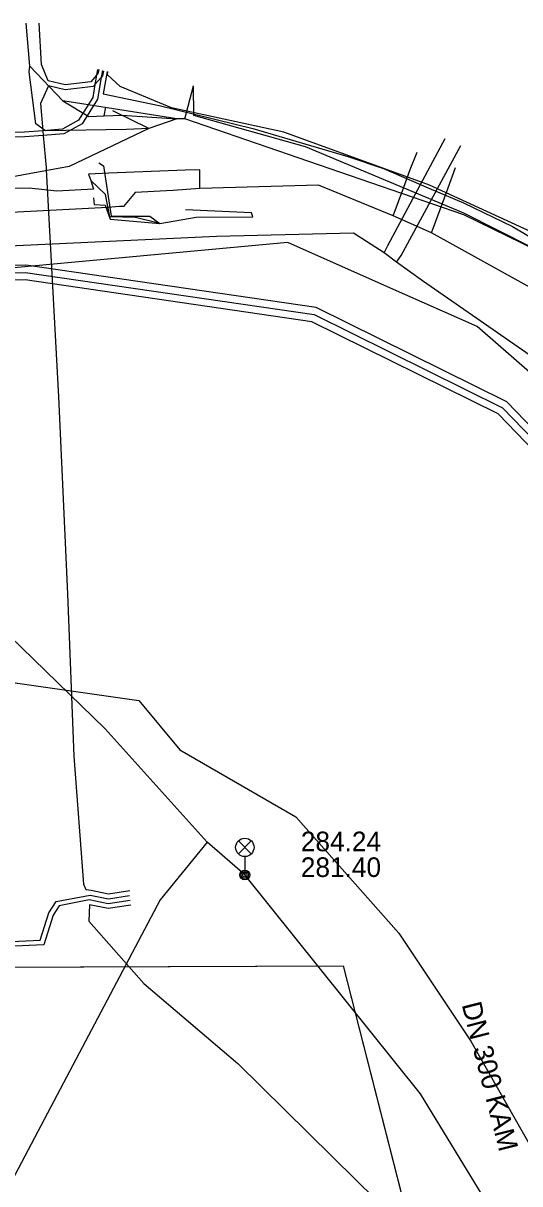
# Model space of a CAD drawing. Extents: x -599854 to -599675, y -1160809 to -1160543.
# Drawn here: x -599765.66 to -599745.4, y -1160591.29 to -1160543.95 of the extents above; entities that cross this region are included whole.
import ezdxf

# ---------------------------------------------------------------- set-up
doc = ezdxf.new("R2010")
doc.units = 0
for name, color, linetype in [('BKOM-ODVODNENI_trasa sítě', 7, 'Continuous'), ('BVK-VODOVOD_trasa sítě', 7, 'Continuous'), ('BVK-VODOVOD_trasa zrušené sítě', 7, 'Continuous'), ('CETIN_kabel podzemní', 7, 'Continuous'), ('CETIN_kabel podzemní neprovozovaný', 7, 'Continuous'), ('DESTOVA-NEPROVOZOVANA_popisy', 7, 'Continuous'), ('DESTOVA_trasa neprovozované sítě', 7, 'Continuous'), ('DPMB_kabel', 7, 'Continuous'), ('DPMB_kyneta', 7, 'Continuous'), ('DSP-JEDNOTNA-BVK_trasa sítě', 7, 'Continuous'), ('EON-NN_kabel', 7, 'Continuous'), ('EON-NN_kabel zrušené sítě', 7, 'Continuous'), ('INNOGY-KABELY_uzemnění', 7, 'Continuous'), ('INNOGY-NTL_trasa sítě', 7, 'Continuous'), ('INNOGY-STL_trasa sítě', 7, 'Continuous'), ('TSB_kabel VO', 7, 'Continuous'), ('TSB_lampy VO', 7, 'Continuous')]:
    doc.layers.add(name, color=color, linetype=linetype)

msp = doc.modelspace()

# ---------------------------------------------------------------- linework, layer by layer
at = {"layer": 'BKOM-ODVODNENI_trasa sítě'}
for points in [[(-599792.21, -1160582.54), (-599790.8, -1160582.535), (-599775.06, -1160582.479), (-599766.92, -1160582.451), (-599752.61, -1160582.4)], [(-599752.61, -1160582.4), (-599748.203, -1160599.656), (-599748.115, -1160600), (-599747.14, -1160603.82)]]:
    msp.add_lwpolyline(points, dxfattribs=at)
at = {"layer": 'BVK-VODOVOD_trasa sítě'}
for points in [[(-599750.93, -1160553.31), (-599750.79, -1160553.02), (-599748.448, -1160548.656)], [(-599750.43, -1160553.69), (-599750.24, -1160553.43), (-599747.809, -1160548.936)], [(-599719.633, -1160602.967), (-599720.5, -1160603.21), (-599721.46, -1160603.05), (-599723.09, -1160601.91), (-599724.27, -1160595.77), (-599725.34, -1160590.19), (-599725.75, -1160588.02), (-599726.33, -1160585.11), (-599727.19, -1160580.77), (-599730.66, -1160575.71), (-599731.23, -1160574.92), (-599731.73, -1160574.22), (-599732.69, -1160572.85), (-599736.99, -1160566.71), (-599739.23, -1160561.6), (-599744.81, -1160557.63), (-599749.37, -1160554.46), (-599750.43, -1160553.69), (-599750.93, -1160553.31), (-599752.19, -1160552.51), (-599757.77, -1160552.65), (-599772.65, -1160553.34)]]:
    msp.add_lwpolyline(points, dxfattribs=at)
at = {"layer": 'BVK-VODOVOD_trasa zrušené sítě'}
msp.add_lwpolyline([(-599723.312, -1160596.189), (-599723.552, -1160595.075), (-599725.385, -1160585.124), (-599727.088, -1160577.648), (-599730.061, -1160573.561), (-599730.185, -1160573.396), (-599730.663, -1160572.731), (-599734.747, -1160567.144), (-599747.147, -1160556.314), (-599750.794, -1160554.698), (-599754.863, -1160552.892), (-599773.118, -1160554.584), (-599787.156, -1160555.886), (-599789.075, -1160557.142), (-599798.149, -1160563.04), (-599806.144, -1160568.237), (-599808.168, -1160571.846), (-599815.66, -1160586.425), (-599816.228, -1160587.481)], dxfattribs=at)
at = {"layer": 'CETIN_kabel podzemní'}
for points in [[(-599765.39, -1160545.7), (-599765.5368, -1160543.9495)], [(-599760.54, -1160548.25), (-599761.45, -1160548.29), (-599764.75, -1160548.34), (-599765.14, -1160548.05), (-599765.42, -1160545.93), (-599765.39, -1160545.7)], [(-599764.05, -1160547.12), (-599765.39, -1160545.7)], [(-599759.07, -1160547.85), (-599758.71, -1160546.51)], [(-599764.05, -1160547.12), (-599762.984, -1160547.756)], [(-599759.39, -1160547.85), (-599764.05, -1160547.12)], [(-599762.353, -1160547.732), (-599762.287, -1160547.377)], [(-599760.54, -1160548.25), (-599762.01, -1160547.53)], [(-599760.54, -1160548.25), (-599763.79, -1160549.79), (-599775.39, -1160551.91), (-599776.73, -1160551.13), (-599777.24, -1160548.01), (-599779.6, -1160547.75), (-599787.47, -1160549.87), (-599795.94, -1160553.78), (-599800.44, -1160556.65), (-599809.68, -1160565.19), (-599817.48, -1160577.77), (-599818.39, -1160579.19)], [(-599762.984, -1160547.756), (-599762.353, -1160547.732)], [(-599762.353, -1160547.732), (-599761.618, -1160547.704)], [(-599761.618, -1160547.704), (-599759.39, -1160547.85)], [(-599759.39, -1160547.85), (-599760.54, -1160548.25)], [(-599759.07, -1160547.85), (-599759.39, -1160547.85)], [(-599743.51, -1160553.8), (-599747.69, -1160551.77), (-599759.07, -1160547.85)], [(-599814.4, -1160581.07), (-599811.3, -1160581.33), (-599803.39, -1160585.07), (-599799.44, -1160586.24), (-599796.45, -1160587.12), (-599794.41, -1160586.52), (-599780.55, -1160576.54), (-599778.97, -1160574.64), (-599776.87, -1160571.64), (-599775.34, -1160571.18), (-599766.27, -1160570.81), (-599760.94, -1160571.57), (-599759.27, -1160573.58), (-599754.54, -1160576.32), (-599750.34, -1160581.07), (-599747.4, -1160585.47), (-599742.37, -1160594.32)]]:
    msp.add_lwpolyline(points, dxfattribs=at)
at = {"layer": 'CETIN_kabel podzemní neprovozovaný'}
for points in [[(-599754.14, -1160548.99), (-599758.7, -1160547.71), (-599758.71, -1160546.51)], [(-599720.38, -1160590.29), (-599722.4, -1160580.45), (-599729.47, -1160568.06), (-599734.57, -1160560.31), (-599743.51, -1160553.8), (-599747.69, -1160551.7), (-599754.14, -1160548.99)]]:
    msp.add_lwpolyline(points, dxfattribs=at)
at = {"layer": 'DESTOVA-NEPROVOZOVANA_popisy'}
msp.add_line((-599754.335, -1160578.772), (-599754.335, -1160578.772), dxfattribs=at)
at = {"layer": 'DESTOVA_trasa neprovozované sítě'}
for points in [[(-599792.25, -1160582.55), (-599790.8, -1160582.535), (-599775.06, -1160582.479), (-599766.92, -1160582.451), (-599752.61, -1160582.4)], [(-599752.61, -1160582.4), (-599748.203, -1160599.656), (-599747.14, -1160603.82)]]:
    msp.add_lwpolyline(points, dxfattribs=at)
at = {"layer": 'DPMB_kabel'}
for points in [[(-599854.3744, -1160570.8811), (-599853.98, -1160571.11), (-599853.34, -1160571.94), (-599850.41, -1160575.09), (-599849.54, -1160575.55), (-599841.94, -1160567.75), (-599841.46, -1160567.86), (-599836.83, -1160571.43), (-599830.31, -1160574.99), (-599826.68, -1160574.81), (-599821.59, -1160577.6), (-599817.92, -1160579.72), (-599816.48, -1160579.55), (-599815.751, -1160578.652), (-599810.91, -1160571.26), (-599805.31, -1160565.16), (-599798.95, -1160559.8), (-599795.69, -1160558.33), (-599784.88, -1160555), (-599775.62, -1160554.42), (-599765.57, -1160554.12), (-599753.796, -1160555.833), (-599746.11, -1160559.64), (-599743.15, -1160562.7)], [(-599854.3744, -1160570.8811), (-599853.98, -1160571.11), (-599853.34, -1160571.94), (-599850.41, -1160575.09), (-599849.54, -1160575.55), (-599841.94, -1160567.75), (-599841.46, -1160567.86), (-599836.83, -1160571.43), (-599830.31, -1160574.99), (-599826.68, -1160574.81), (-599821.59, -1160577.6), (-599817.92, -1160579.72), (-599816.48, -1160579.55), (-599815.751, -1160578.652), (-599810.91, -1160571.26), (-599805.31, -1160565.16), (-599798.95, -1160559.8), (-599795.69, -1160558.33), (-599784.88, -1160555), (-599775.62, -1160554.42), (-599765.57, -1160554.12), (-599753.796, -1160555.833), (-599746.11, -1160559.64), (-599743.15, -1160562.7)], [(-599742.967, -1160562.458), (-599745.93, -1160559.394), (-599753.706, -1160555.543), (-599765.553, -1160553.819), (-599775.629, -1160554.12), (-599775.639, -1160554.121), (-599784.934, -1160554.703), (-599795.796, -1160558.049), (-599799.111, -1160559.544), (-599805.518, -1160564.943)], [(-599742.967, -1160562.458), (-599745.93, -1160559.394), (-599753.706, -1160555.543), (-599765.553, -1160553.819), (-599775.629, -1160554.12), (-599775.639, -1160554.121), (-599784.934, -1160554.703), (-599795.796, -1160558.049), (-599799.111, -1160559.544), (-599805.518, -1160564.943)]]:
    msp.add_lwpolyline(points, dxfattribs=at)
at = {"layer": 'DPMB_kyneta'}
msp.add_lwpolyline([(-599679.2237, -1160588.7865), (-599682.09, -1160589.515), (-599685.576, -1160587.065), (-599686.493, -1160586.917), (-599689.402, -1160587.72), (-599697.166, -1160589.741), (-599712.717, -1160593.601), (-599718.397, -1160595.039), (-599721.496, -1160595.147), (-599723.319, -1160593.689), (-599724.625, -1160587.968), (-599724.995, -1160585.706), (-599726.218, -1160580.085), (-599729.152, -1160573.2), (-599732.987, -1160568.044), (-599737.527, -1160565.171), (-599740.396, -1160564.524), (-599743.333, -1160562.942), (-599746.29, -1160559.886), (-599753.886, -1160556.123), (-599765.587, -1160554.421), (-599775.611, -1160554.72)], dxfattribs=at)
at = {"layer": 'DSP-JEDNOTNA-BVK_trasa sítě'}
for p, q in [((-599766.92, -1160582.451), (-599752.61, -1160582.4)), ((-599752.61, -1160582.4), (-599748.203, -1160599.656))]:
    msp.add_line(p, q, dxfattribs=at)
at = {"layer": 'EON-NN_kabel'}
for points in [[(-599762.571, -1160545.835), (-599762.61, -1160546.009), (-599762.668, -1160546.074), (-599762.9, -1160546.335), (-599763.944, -1160546.459), (-599764.638, -1160546.297), (-599764.92, -1160545.63), (-599765.0119, -1160543.9495)], [(-599762.627, -1160545.843), (-599762.668, -1160546.074), (-599762.734, -1160546.449), (-599762.827, -1160546.981), (-599763.401, -1160547.905), (-599764.06, -1160548.272), (-599764.861, -1160548.333), (-599765.604, -1160548.39), (-599775.822, -1160548.41), (-599777.168, -1160548.46), (-599777.735, -1160548.413), (-599778.972, -1160547.542), (-599779.425, -1160547.223), (-599779.55, -1160546.69), (-599779.292, -1160545.175)], [(-599762.43, -1160545.88), (-599762.48, -1160546.163), (-599762.636, -1160547.054), (-599763.259, -1160548.055), (-599764, -1160548.468), (-599764.843, -1160548.532), (-599765.596, -1160548.59), (-599775.818, -1160548.61), (-599777.172, -1160548.66), (-599777.805, -1160548.607), (-599778.97, -1160547.788), (-599779.554, -1160547.378), (-599780.24, -1160547.41), (-599781.14, -1160547.4), (-599782.57, -1160547.64), (-599785.1, -1160548.35), (-599788.12, -1160549.35), (-599790.53, -1160550.26), (-599792.84, -1160551.23), (-599794.8, -1160552.33), (-599796.78, -1160553.49), (-599801.45, -1160556.33)], [(-599762.233, -1160545.917), (-599762.394, -1160546.831), (-599760.12, -1160547.31), (-599756.29, -1160548.25), (-599752.42, -1160549.39), (-599750.97, -1160549.88), (-599749.11, -1160550.68), (-599747.7, -1160551.28), (-599745.7, -1160552.24), (-599742.59, -1160554.08)], [(-599744.73, -1160552.56), (-599749.09, -1160550.55), (-599755.03, -1160548.4), (-599759.61, -1160547.4), (-599761.71, -1160546.53), (-599762.22, -1160546.051), (-599762.204, -1160545.919)]]:
    msp.add_lwpolyline(points, dxfattribs=at)
at = {"layer": 'EON-NN_kabel zrušené sítě'}
for points in [[(-599778.9929, -1160543.9495), (-599778.972, -1160547.542), (-599778.97, -1160547.788), (-599778.95, -1160551.18), (-599778.49, -1160561.13), (-599778.22, -1160569.41), (-599777.9, -1160577.56), (-599775.38, -1160580.14), (-599774.82, -1160580.27), (-599774.4, -1160580.52), (-599773.962, -1160581.651), (-599773.414, -1160581.74), (-599764.965, -1160581.343), (-599764.621, -1160580.237), (-599764.322, -1160579.771), (-599762.931, -1160579.512), (-599762.188, -1160579.659), (-599761.325, -1160579.531)], [(-599762.38, -1160545.9), (-599762.425, -1160546.101), (-599762.48, -1160546.163), (-599762.734, -1160546.449), (-599762.8, -1160546.525), (-599763.956, -1160546.661), (-599764.632, -1160546.502), (-599764.96, -1160547.22), (-599764.861, -1160548.333), (-599764.843, -1160548.532), (-599764.728, -1160549.828), (-599764.72, -1160549.92), (-599764.22, -1160559.19), (-599763.85, -1160567.22), (-599763.6, -1160573.84), (-599763.2, -1160579.06), (-599763.101, -1160579.279), (-599762.892, -1160579.316), (-599762.183, -1160579.456), (-599761.312, -1160579.327)], [(-599761.295, -1160579.729), (-599762.192, -1160579.861), (-599762.969, -1160579.708), (-599764.198, -1160579.949), (-599764.439, -1160580.323), (-599764.815, -1160581.537), (-599773.426, -1160581.94), (-599774.387, -1160581.787), (-599776.84, -1160581.93), (-599777.35, -1160581.67), (-599777.61, -1160581.25), (-599778.45, -1160579.98), (-599783.57, -1160579.17), (-599790.74, -1160579.06), (-599796.77, -1160578.86), (-599802.11, -1160578.86)], [(-599761.266, -1160579.927), (-599762.197, -1160580.064), (-599762.963, -1160579.913), (-599762.99, -1160580.57), (-599760.74, -1160583.12), (-599756.91, -1160586.38), (-599752.09, -1160591.12), (-599747.43, -1160595.7), (-599744.03, -1160598.67)]]:
    msp.add_lwpolyline(points, dxfattribs=at)
at = {"layer": 'INNOGY-KABELY_uzemnění'}
for points in [[(-599762.57, -1160549.64), (-599762.39, -1160549.77), (-599762.07, -1160551.82), (-599760.49, -1160551.82), (-599760.09, -1160552.12)], [(-599760.09, -1160552.12), (-599761.08, -1160551.88), (-599762.13, -1160551.85), (-599762.3, -1160550.93), (-599762.899, -1160550.371)], [(-599762.8, -1160551.07), (-599762.77, -1160551.35), (-599762.32, -1160551.37), (-599762.11, -1160551.94), (-599760.09, -1160552.12), (-599758.6, -1160551.86), (-599756.3, -1160551.85), (-599756.35, -1160551.68), (-599759.04, -1160551.56)]]:
    msp.add_lwpolyline(points, dxfattribs=at)
at = {"layer": 'INNOGY-NTL_trasa sítě'}
msp.add_lwpolyline([(-599762.899, -1160550.371), (-599762.79, -1160550.72), (-599764.29, -1160550.8), (-599765.418, -1160550.679), (-599767.231, -1160550.694), (-599767.869, -1160550.747), (-599768.28, -1160550.753)], dxfattribs=at)
at = {"layer": 'INNOGY-STL_trasa sítě'}
for points in [[(-599750.57, -1160551.81), (-599750.14, -1160550.64), (-599749.87, -1160549.91), (-599749.59, -1160549.21)], [(-599758.46, -1160550.69), (-599758.46, -1160549.93), (-599759.05, -1160549.95), (-599762.17, -1160550.07)], [(-599749, -1160552.5), (-599748.48, -1160551.07), (-599748.33, -1160550.66), (-599748.031, -1160549.84)], [(-599762.17, -1160550.07), (-599763, -1160550.1), (-599762.899, -1160550.371)], [(-599739.31, -1160557.87), (-599749, -1160552.5), (-599750.57, -1160551.81), (-599753.61, -1160550.56), (-599758.46, -1160550.69), (-599759.54, -1160550.77), (-599759.82, -1160550.78), (-599761.09, -1160550.86), (-599761.57, -1160551.42), (-599761.73, -1160551.43)], [(-599761.73, -1160551.43), (-599762.21, -1160551.46), (-599780.39, -1160552.41), (-599780.99, -1160552.44)]]:
    msp.add_lwpolyline(points, dxfattribs=at)
at = {"layer": 'TSB_kabel VO'}
for points in [[(-599766.71, -1160568.47), (-599762.32, -1160572.73), (-599758.16, -1160577.35), (-599760.07, -1160579.7), (-599764.277, -1160587.66), (-599769.44, -1160597.43)], [(-599712.85, -1160612.2), (-599713.231, -1160610.818), (-599715.05, -1160611.32), (-599720.13, -1160612.91), (-599729.8, -1160616.03), (-599730.26, -1160617.21), (-599734.33, -1160617.68), (-599739.29, -1160617.63), (-599739.48, -1160618.61), (-599740.14, -1160618.47), (-599744.95, -1160617.17), (-599744.01, -1160615.53), (-599741.64, -1160607.33), (-599740.03, -1160599.74), (-599742.84, -1160597.94), (-599743.59, -1160597.21), (-599749.46, -1160587.62), (-599756.62, -1160578.69), (-599758.16, -1160577.35), (-599762.32, -1160572.73), (-599766.71, -1160568.47)]]:
    msp.add_lwpolyline(points, dxfattribs=at)
at = {"layer": 'TSB_lampy VO'}
for p, q in [((-599756.885, -1160577.83), (-599756.355, -1160577.3)), ((-599756.885, -1160577.3), (-599756.355, -1160577.83)), ((-599756.885, -1160577.83), (-599756.355, -1160577.3)), ((-599756.885, -1160577.3), (-599756.355, -1160577.83)), ((-599756.62, -1160577.94), (-599756.62, -1160578.69)), ((-599756.62, -1160577.94), (-599756.62, -1160578.69))]:
    msp.add_line(p, q, dxfattribs=at)
for centre, radius in [((-599756.62, -1160577.565), 0.375), ((-599756.62, -1160577.565), 0.375), ((-599756.62, -1160578.69), 0.2), ((-599756.62, -1160578.69), 0.2), ((-599756.62, -1160578.69), 0.1445), ((-599756.62, -1160578.69), 0.1445), ((-599756.62, -1160578.69), 0.0876), ((-599756.62, -1160578.69), 0.0876)]:
    msp.add_circle(centre, radius, dxfattribs=at)

# ---------------------------------------------------------------- texts
at = {"layer": 'DESTOVA-NEPROVOZOVANA_popisy'}
for s, p in [('284.24', (-599754.335, -1160577.722)), ('281.40', (-599754.335, -1160578.772))]:
    msp.add_text(s, height=0.8, dxfattribs=at).set_placement(p)
msp.add_text('DN 300 KAM', height=0.8, rotation=284.32539, dxfattribs=at).set_placement((-599747.777, -1160583.974))

doc.saveas('drawing.dxf')
